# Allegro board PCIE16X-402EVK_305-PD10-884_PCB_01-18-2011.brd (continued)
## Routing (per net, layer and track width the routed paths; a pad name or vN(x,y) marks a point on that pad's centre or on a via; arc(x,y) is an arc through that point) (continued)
VIN1_2: length 48.1
  TOP w0.229: 80.58,35.2 79.84,35.2 79.83,35.19 v1(79.26,35.19) U2.24 ; U1.24 v1(63.26,35.19)
  TOP w0.635: 80.58,35.2 81.98,35.2
  TOP w0.762: v1(92.19,27.96) 89.83,27.96 87.49,30.3 87.49,32.51 84.8,35.2 81.98,35.2
  POWER1 w0.229: 64.58,35.2 64.58,35.19 v1(63.26,35.19) ; 78.4,35.19 v1(79.26,35.19)
  POWER1 w0.292: 64.58,35.2 65.13,35.2 65.43,35.49 ; 78.04,35.19 78.4,35.19
  POWER1 w0.508: 77.33,36.83 77.62,36.53 77.62,35.47 77.9,35.19 78.04,35.19
  POWER1 w0.635: 65.43,35.49 66.03,36.09 66.03,36.73
  POWER1 w0.762: 66.03,36.73 66.03,37.44 66.89,38.3 68.54,38.3 69.63,37.21 76.95,37.21 77.33,36.83
  BOTTOM w0.762: v1(92.19,27.96) 94.74,25.41 C160.2 95.86,25.41 96.25,25.8 97.47,25.8 97.51,25.84 C21.2
VIN3_4: length 46.4
  TOP w0.229: U3.24 v1(113.83,35.19) ; U4.24 v1(129.83,35.19)
  BOTTOM w0.229: 115.15,35.19 v1(113.83,35.19)
  BOTTOM w0.292: 115.15,35.19 115.63,35.19 116.4,35.96 116.4,37.59 117.08,38.27 ; v1(129.83,35.19) 129.8,35.23 129.02,35.23 128.38,35.86 128.38,36.47
  BOTTOM w0.635: 128.38,36.47 128.38,37.31 127.69,38.01
  BOTTOM w0.762: 127.69,38.01 126.02,39.67 118.48,39.67 117.08,38.27 ; C161.2 97.08,40.65 J5.2 97.69,41.08 C22.2 v1(101.08,41.08) 111.05,41.08 112.89,39.24 112.89,35.58 113.28,35.19 v1(113.83,35.19)
3_3V: length 25.6
  TOP w0.508: v1(52.51,57.48) 52.51,58.33 52.65,58.47 J2.B8 ; J1.B8 52.65,6.62 v1(52.34,6.93) ; U5.4 v1(86.8,18.69)
  BOTTOM w0.305: v1(54.06,7.52) 53.65,7.1 J1.A9
  BOTTOM w0.381: R6.1 v1(86.17,41.55)
  BOTTOM w0.508: v1(86.8,18.69) 86.69,18.8 C23.2 ; J2.A9 v1(53.65,57.73) ; J2.A10 v1(54.65,57.76) ; v1(54.12,6.8) 54.65,6.27 J1.A10
  BOTTOM w0.635: v1(52.51,57.48) 52.76,57.73 v1(53.65,57.73) 54.62,57.73 v1(54.65,57.76) ; R3.1 v1(88.53,22.88)
  vias: v1(82.11,36.73) v1(82.74,36.73) v1(83.5,36.73)
3_3VAUX: length 66.4
  TOP w0.292: J2.B10 54.65,58.59 55.18,58.06 55.18,57.3 54.14,56.26 50.61,56.26 46.01,51.66 46.01,16.99 54.65,8.35 J1.B10
A_D1: length 130.8
  TOP w0.229: 63.23,36.98 62.95,36.69 U1.27
  TOP w0.254: R7.2 v1(87.91,49.07)
  TOP w0.292: 63.23,36.98 63.31,37.06 v1(63.84,37.06) ; SW9.8 v1(140.66,20)
  POWER1 w0.292: v1(87.91,49.07) 82.49,49.07 74.59,41.17 65.82,41.17 63.84,39.19 v1(63.84,37.06) 63.23,37.06 62.67,36.5 62.67,30.07 68.49,24.25 124.27,24.25 127.65,27.63 139.31,27.63 140.65,26.29 140.65,20 v1(140.66,20)
A_D2: length 124.6
  TOP w0.229: U2.27 v1(79.99,36.69)
  TOP w0.254: R8.2 v1(87.01,47.62)
  TOP w0.292: SW9.7 143.67,22.54 v1(144.06,22.15)
  POWER1 w0.292: v1(150.81,41.86) 135.45,41.86 132.73,44.57 103.31,44.57 98.46,39.72 92.39,39.72 90.53,37.87 81.17,37.87 v1(79.99,36.69) 79.16,37.52 79.16,43.61 83.17,47.62 v1(87.01,47.62)
  BOTTOM w0.292: v1(144.06,22.15) 144.13,22.07 149.85,22.07 153.38,25.6 153.38,39.29 v1(150.81,41.86)
A_D3: length 51.2
  TOP w0.229: U3.27 v1(114.56,36.69)
  TOP w0.254: v1(135.27,40.43) 134.72,39.89 R9.2
  TOP w0.292: R9.2 134.05,26.03 135.51,24.57 140.16,24.57 140.66,25.08 SW9.6
  BOTTOM w0.292: v1(114.56,36.69) 114.56,40.01 116.18,41.63 116.2,41.63 116.22,41.64 133.82,41.64 133.84,41.63 134.07,41.63 v1(135.27,40.43)
A_D4: length 27.1
  TOP w0.229: U4.27 v1(130.56,36.69)
  TOP w0.254: R10.2 v1(137.88,40.01)
  TOP w0.292: SW9.5 142.28,27.63 140.14,27.63 138.01,29.77 138.01,37.89 136.97,38.93 R10.2
  BOTTOM w0.292: v1(130.56,36.69) 131.3,36.69 134,39.39 137.26,39.39 v1(137.88,40.01)
DEMA0_SDA: length 139
  TOP w0.229: U4.49 v1(118.2,35.19) ; U3.49 v1(102.2,35.19) ; U1.49 v1(51.62,35.19) ; U2.49 v1(67.63,35.19)
  TOP w0.292: SW3.12 SW3.10 22.67,37.61 23.41,36.88 33.41,36.88 42.23,45.69 SW4.1 v1(42.23,49.82)
  POWER1 w0.229: 116.88,35.19 v1(118.2,35.19)
  POWER1 w0.292: v1(102.2,35.19) 102.75,35.19 102.98,35.43 103,35.43 103.33,35.76 103.33,35.77 103.34,35.79 103.34,37.46 104.84,38.96 114.62,38.96 115.56,38.02 115.56,36.31 116.68,35.19 116.88,35.19 ; v1(42.23,49.82) 42.23,48.1 52.17,38.16 52.17,35.74 v1(51.62,35.19)
  BOTTOM w0.229: v1(102.2,35.19) 100.88,35.19 ; 66.31,35.19 v1(67.63,35.19)
  BOTTOM w0.292: v1(51.62,35.19) 52.46,35.19 52.87,35.61 52.87,37.79 54.64,39.56 62.81,39.56 65.03,37.34 65.03,35.89 65.73,35.2 66.15,35.2 66.16,35.19 66.31,35.19 ; 100.88,35.19 100.38,35.19 98.11,37.46 80.86,37.46 79.02,39.3 70.64,39.3 69.01,37.68 69.01,35.88 68.9,35.77 68.9,35.76 68.34,35.2 67.63,35.2 v1(67.63,35.19)
DEMA1_SCL: length 141
  TOP w0.229: U2.50 v1(66.9,34.69) ; U4.50 v1(117.47,34.69) ; U3.50 v1(101.47,34.69) ; U1.50 v1(50.9,34.69)
  TOP w0.292: 25.21,39.37 SW3.8 SW3.7 30.48,39.19 33.44,39.19 39.69,45.44 SW4.2 v1(39.69,49.89)
  POWER1 w0.229: 51.93,34.7 51.93,34.69 v1(50.9,34.69)
  POWER1 w0.292: 51.93,34.7 52.29,34.7 52.68,35.09 52.68,38.3 52.69,38.31 52.69,38.76 44.77,46.68 44.77,48.46 42.56,50.67 40.46,50.67 v1(39.69,49.89)
  BOTTOM w0.229: 102.48,34.7 101.47,34.7 v1(101.47,34.69) ; v1(50.9,34.69) 52.01,34.69 ; v1(66.9,34.69) 68.42,34.69
  BOTTOM w0.292: 52.01,34.69 52.72,34.69 53.38,35.35 53.38,37.46 54.97,39.05 62.6,39.05 64.52,37.13 64.52,35.68 65.52,34.69 66.89,34.69 v1(66.9,34.69) ; v1(117.47,34.69) 116.95,34.69 115.56,33.3 115.56,32.51 115,31.95 113.27,31.95 112.13,33.09 112.13,38.43 111.39,39.16 104.48,39.16 103.65,38.33 103.65,35.48 102.86,34.7 102.48,34.7 ; v1(101.47,34.69) 99.91,34.69 98.67,35.94 81.62,35.94 78.77,38.8 70.97,38.8 69.51,37.33 69.51,35.63 68.57,34.69 68.42,34.69
DEMB0_AD1: length 117.1
  TOP w0.229: U4.53 v1(118.2,33.19) ; U1.53 v1(51.62,33.19) ; U3.53 v1(102.2,33.19) ; U2.53 v1(67.63,33.19)
  TOP w0.292: 17.84,26.55 SW5.11 22.92,26.55 v1(22.92,28.34)
  POWER1 w0.229: 50.23,33.19 v1(51.62,33.19)
  POWER1 w0.292: v1(22.92,28.34) 28.36,33.78 49.64,33.78 50.23,33.19
  BOTTOM w0.229: v1(118.2,33.19) 118.2,33.19 117.21,33.19 116.88,32.86 ; v1(67.63,33.19) 66.41,33.19 66.31,33.09 ; 100.96,33.19 v1(102.2,33.19)
  BOTTOM w0.292: v1(102.2,33.19) 105.47,29.92 115.1,29.92 116.8,31.62 116.8,32.79 116.88,32.86 ; v1(67.63,33.19) 68.42,33.19 71.73,29.88 85.01,29.88 86.3,31.16 97.35,31.16 99.38,33.19 100.96,33.19 ; 66.31,33.09 63.3,30.08 54.71,30.08 51.62,33.17 v1(51.62,33.19)
DEMB1_AD0: length 110
  TOP w0.229: U1.54 v1(50.9,32.69) ; U2.54 v1(66.9,32.69) ; U4.54 v1(117.47,32.69) ; U3.54 v1(101.47,32.69)
  TOP w0.292: v1(31.72,26.55) SW5.7 SW5.9
  POWER1 w0.292: v1(31.72,26.55) 35.5,30.32 47.05,30.32 49.42,32.69 v1(50.9,32.69)
  BOTTOM w0.292: v1(117.47,32.69) 117.47,31.32 115.51,29.36 105.23,29.36 101.89,32.69 v1(101.47,32.69) 99.78,32.69 97.62,30.53 94.07,30.53 92.93,29.38 71.46,29.38 68.19,32.66 67.85,32.66 67.85,32.66 67.4,32.66 67.4,32.66 66.93,32.66 v1(66.9,32.69) 63.78,29.58 54.01,29.58 v1(50.9,32.69)
ENSMB: length 122.3
  TOP w0.229: U3.48 v1(101.47,35.69) ; U2.48 v1(66.9,35.69) ; U4.48 v1(117.47,35.69) ; U1.48 v1(50.9,35.69)
  TOP w0.292: v1(27.37,43.09) SW2.6 SW2.5 SW2.4
  POWER1 w0.229: v1(101.47,35.69) 102.56,35.69 102.79,35.92
  POWER1 w0.292: v1(27.37,43.09) 35.56,43.09 42.96,35.69 v1(50.9,35.69) ; v1(117.47,35.69) 117.44,35.72 116.89,35.72 116.17,36.45 116.17,38.3 115,39.47 104.46,39.47 102.83,37.84 102.83,35.96 102.79,35.92
  BOTTOM w0.229: v1(50.9,35.69) 51.88,35.69 ; 68.31,35.89 68.12,35.69 v1(66.9,35.69)
  BOTTOM w0.292: v1(66.9,35.69) 66.17,35.69 65.54,36.33 65.54,37.59 63.06,40.07 54.33,40.07 52.36,38.1 52.36,35.94 52.12,35.69 51.88,35.69 ; 68.31,35.89 68.52,36.09 68.52,38.07 70.27,39.82 79.22,39.82 81.07,37.97 98.62,37.97 100.88,35.71 101.45,35.71 v1(101.47,35.69)
EQA0: length 121.6
  TOP w0.229: U3.20 v1(113.83,33.19) ; U2.20 v1(79.26,33.19) ; U4.20 v1(129.83,33.19) ; U1.20 v1(63.26,33.19)
  TOP w0.292: SW11.12 SW11.11 SW11.10 v1(154.19,24.78)
  POWER1 w0.229: 131.15,33.4 130.95,33.19 v1(129.83,33.19) ; v1(113.83,33.19) 113.83,33.19 114.85,33.19 ; v1(63.26,33.19) 64.3,33.19 64.58,32.92 ; v1(79.26,33.19) 80.58,33.19
  POWER1 w0.292: v1(113.83,33.19) 113.83,32.15 111.65,29.97 84.87,29.97 81.65,33.19 80.58,33.19 ; v1(154.19,24.78) 154.19,30.61 151.83,32.97 143.57,32.97 140.93,35.61 133.36,35.61 131.15,33.4 ; 114.85,33.19 115.1,33.19 115.76,32.53 115.76,31.52 117.46,29.82 127.14,29.82 129.81,32.48 129.81,33.17 v1(129.83,33.19) ; 64.58,32.92 64.76,32.74 64.76,31.14 66.69,29.21 76.59,29.21 79.26,31.88 v1(79.26,33.19)
EQA1: length 114.8
  TOP w0.229: U4.19 v1(130.56,32.69) ; U3.19 v1(114.56,32.69) ; U2.19 v1(79.99,32.69) ; U1.19 v1(63.99,32.69)
  TOP w0.292: SW11.9 SW11.8 SW11.7 v1(152.17,31.43)
  POWER1 w0.292: v1(63.99,32.69) 63.99,30.99 66.28,28.7 76.85,28.7 79.77,31.62 79.77,32.47 v1(79.99,32.69) 80,32.69 81.42,32.69 84.57,29.54 84.61,29.54 84.67,29.47 111.85,29.47 111.92,29.54 111.98,29.54 114.36,31.92 114.36,32.5 v1(114.56,32.69) 114.81,32.69 115.25,32.25 115.25,31.16 117.11,29.31 127.88,29.31 130.56,31.99 v1(130.56,32.69) 130.59,32.72 132.31,32.72 134.46,30.58 151.31,30.58 v1(152.17,31.43)
EQB0_AD3: length 123.9
  TOP w0.229: U1.46 v1(50.9,36.69) ; U4.46 v1(117.47,36.69) ; U2.46 v1(66.9,36.69) ; U3.46 v1(101.47,36.69)
  TOP w0.292: v1(32.77,55.29) SW1.12 SW1.11 SW1.10
  POWER1 w0.292: v1(32.77,55.29) 32.77,51.41 47.47,36.71 50.88,36.71 v1(50.9,36.69) ; v1(117.47,36.69) 117.47,38.78 115.76,40.48 103.39,40.48 101.47,38.56 v1(101.47,36.69)
  BOTTOM w0.292: v1(101.47,36.69) 98.51,39.65 93.99,39.65 91.05,42.59 78.32,42.59 76.62,40.89 69.51,40.89 67.25,38.63 67.25,37 66.92,36.67 v1(66.9,36.69) 66.56,37.03 66.56,38 63.33,41.23 53.95,41.23 50.9,38.18 v1(50.9,36.69)
EQB1_AD2: length 126.2
  TOP w0.229: U4.47 v1(118.2,36.19) ; U1.47 v1(51.62,36.19) ; U3.47 v1(102.2,36.19) ; U2.47 v1(67.63,36.19)
  TOP w0.292: SW1.7 SW1.8 SW1.9 v1(25.08,55.29)
  POWER1 w0.229: 50.23,36.19 v1(51.62,36.19) ; v1(118.2,36.19) 117.21,36.19 116.88,36.52
  POWER1 w0.292: 50.23,36.19 44.21,36.19 25.12,55.29 v1(25.08,55.29) ; 116.88,36.52 116.68,36.73 116.68,38.71 115.41,39.98 104.15,39.98 102.2,38.02 v1(102.2,36.19)
  BOTTOM w0.229: v1(102.2,36.19) 101.1,36.19 100.88,36.41 ; 66.31,36.5 66.61,36.19 v1(67.63,36.19)
  BOTTOM w0.292: v1(51.62,36.19) 51.62,36.8 51.63,36.8 51.63,38.12 54.17,40.67 63.18,40.67 66.05,37.8 66.05,36.76 66.31,36.5 ; v1(67.63,36.19) 67.78,36.35 67.78,38.27 69.84,40.33 79.43,40.33 80.6,39.16 93.78,39.16 93.79,39.15 98.14,39.15 100.88,36.41
JTAG1: length 65
  TOP w0.292: J2.B9 53.65,58.61 53.12,58.08 53.12,57.22 52.68,56.79 50.18,56.79 45.38,51.99 45.38,16.43 53.26,8.55 53.26,6.44 53.65,6.05 J1.B9
JTAG2: length 66.7
  BOTTOM w0.292: J1.A5 49.65,13.38 37.61,25.42 37.61,43.58 49.65,55.63 J2.A5
JTAG3: length 67
  BOTTOM w0.292: J2.A6 50.65,58.46 50.15,57.95 50.15,55.01 38.27,43.13 38.27,25.98 50.2,14.04 50.2,6.36 50.65,5.91 J1.A6
JTAG4: length 67.2
  BOTTOM w0.292: J2.A7 51.65,58.67 50.64,57.66 50.64,54.56 38.95,42.87 38.95,26.31 51.02,14.25 51.02,6.5 51.65,5.86 J1.A7
JTAG5: length 67.6
  BOTTOM w0.292: J1.A8 52.65,5.79 52.87,6.01 52.87,13.38 39.69,26.57 39.69,42.72 51.72,54.75 51.72,57.78 52.65,58.7 J2.A8
LPBK: length 138.1
  TOP w0.229: U2.23 v1(79.99,34.69) ; U4.23 v1(130.56,34.69) ; U3.23 v1(114.56,34.69) ; U1.23 v1(63.99,34.69)
  TOP w0.292: v1(139.03,57.25) SW6.9 SW6.8 SW6.7
  POWER1 w0.229: 78.02,34.36 78.35,34.69 v1(79.99,34.69) ; 112.73,34.45 112.97,34.69 v1(114.56,34.69)
  POWER1 w0.292: 112.73,34.45 112.73,34.45 112.18,33.9 112.18,33.04 111.42,32.28 106.53,32.28 105.72,31.47 91.25,31.47 90.42,32.3 84.8,32.3 82.41,34.69 v1(79.99,34.69) ; 78.02,34.36 75.58,31.92 66.84,31.92 66.31,32.46 66.31,33.53 65.68,34.16 65.14,34.7 64,34.7 v1(63.99,34.69)
  BOTTOM w0.229: v1(130.56,34.69) 129.2,34.69
  BOTTOM w0.292: v1(114.56,34.69) 114.61,34.64 116.2,34.64 116.75,35.19 116.75,35.2 116.94,35.39 116.94,36.91 116.95,36.92 116.95,36.95 118.81,38.81 125.04,38.81 127.65,36.19 127.65,36.17 127.8,36.02 127.8,35.72 128.79,34.73 128.83,34.73 128.87,34.69 129.2,34.69 ; v1(139.03,57.25) 139.03,53.95 149.06,43.92 149.06,35.88 147.76,34.59 145.66,34.59 142.08,38.17 134.84,38.17 131.36,34.69 v1(130.56,34.69)
PERN0: length 4
  TOP w0.203: C64.1 52.31,28.9 52.31,29.91 53.67,31.27 53.67,32.02 U1.2
PERN0_C: length 3.9
  TOP w0.203: U1.44 53.67,37.36 53.67,38.3 52.34,39.63 52.34,40.51 C128.1
PERN1: length 3.8
  TOP w0.203: U1.4 54.67,32.02 54.67,30.87 53.84,30.03 53.84,28.9 C66.1
PERN1_C: length 3.8
  TOP w0.203: C130.1 53.84,40.49 53.84,39.53 54.67,38.7 54.67,37.36 U1.42
PERN2: length 3.5
  TOP w0.203: C68.1 55.39,28.87 55.39,30.16 55.67,30.45 55.67,32.02 U1.6
PERN2_C: length 3.7
  TOP w0.203: C132.1 55.36,40.49 55.36,39.63 56.17,38.82 56.17,37.36 U1.39
PERN3: length 3.5
  TOP w0.203: C70.1 56.93,28.85 56.93,30.1 56.67,30.36 56.67,32.02 U1.8
PERN3_C: length 3.5
  TOP w0.203: C134.1 56.88,40.49 56.88,39.45 57.17,39.17 57.17,37.36 U1.37
PERN4: length 4
  TOP w0.203: C72.1 68.31,28.9 68.31,29.86 69.67,31.21 69.67,32.02 U2.2
PERN4_C: length 3.9
  TOP w0.203: C136.1 68.34,40.51 68.34,39.63 69.67,38.3 69.67,37.36 U2.44
PERN5: length 3.8
  TOP w0.203: C74.1 69.84,28.9 69.84,29.98 70.67,30.82 70.67,32.02 U2.4
PERN5_C: length 3.8
  TOP w0.203: U2.42 70.67,37.36 70.67,38.7 69.84,39.53 69.84,40.49 C138.1
PERN6: length 3.5
  TOP w0.203: U2.6 71.67,32.02 71.67,30.45 71.39,30.16 71.39,28.87 C76.1
PERN6_C: length 3.7
  TOP w0.203: U2.39 72.17,37.36 72.17,38.82 71.36,39.63 71.36,40.49 C140.1
PERN7: length 3.5
  TOP w0.203: C78.1 72.94,28.85 72.94,30.1 72.67,30.36 72.67,32.02 U2.8
PERN7_C: length 3.5
  TOP w0.203: C142.1 72.89,40.49 72.89,39.45 73.17,39.17 73.17,37.36 U2.37
PERN8: length 4
  TOP w0.203: C80.1 102.88,28.9 102.88,29.86 104.24,31.21 104.24,32.02 U3.2
PERN8_C: length 3.9
  TOP w0.203: U3.44 104.24,37.36 104.24,38.3 102.91,39.63 102.91,40.51 C144.1
PERN9: length 3.8
  TOP w0.203: U3.4 105.24,32.02 105.24,30.82 104.41,29.98 104.41,28.9 C82.1
PERN9_C: length 3.8
  TOP w0.203: C146.1 104.41,40.49 104.41,39.53 105.24,38.7 105.24,37.36 U3.42
PERN10: length 3.5
  TOP w0.203: C84.1 105.96,28.87 105.96,30.16 106.24,30.45 106.24,32.02 U3.6
PERN10_C: length 3.7
  TOP w0.203: C148.1 105.93,40.49 105.93,39.63 106.74,38.82 106.74,37.36 U3.39
PERN11: length 3.5
  TOP w0.203: U3.8 107.24,32.02 107.24,30.36 107.51,30.1 107.51,28.85 C86.1
PERN11_C: length 3.5
  TOP w0.203: C150.1 107.46,40.49 107.46,39.45 107.74,39.17 107.74,37.36 U3.37
PERN12: length 4
  TOP w0.203: C88.1 118.89,28.9 118.89,29.86 120.24,31.21 120.24,32.02 U4.2
PERN12_C: length 3.9
  TOP w0.203: C152.1 118.91,40.51 118.91,39.63 120.24,38.3 120.24,37.36 U4.44
PERN13: length 3.8
  TOP w0.203: C90.1 120.41,28.9 120.41,29.98 121.24,30.82 121.24,32.02 U4.4
PERN13_C: length 3.8
  TOP w0.203: C154.1 120.41,40.49 120.41,39.53 121.24,38.7 121.24,37.36 U4.42
PERN14: length 3.5
  TOP w0.203: U4.6 122.24,32.02 122.24,30.45 121.96,30.16 121.96,28.87 C92.1
PERN14_C: length 3.7
  TOP w0.203: U4.39 122.74,37.36 122.74,38.82 121.93,39.63 121.93,40.49 C156.1
PERN15: length 3.5
  TOP w0.203: U4.8 123.24,32.02 123.24,30.36 123.51,30.1 123.51,28.85 C94.1
PERN15_C: length 3.5
  TOP w0.203: U4.37 123.74,37.36 123.74,39.17 123.46,39.45 123.46,40.49 C158.1
PERP0: length 3.9
  TOP w0.203: C63.1 51.85,28.85 51.85,30.1 53.21,31.46 53.21,32.02 U1.1
PERP0_C: length 3.9
  TOP w0.203: C127.1 51.88,40.51 51.88,39.44 53.21,38.11 53.21,37.36 U1.45
PERP1: length 3.7
  TOP w0.203: C65.1 53.38,28.85 53.38,30.22 54.21,31.06 54.21,32.02 U1.3
PERP1_C: length 3.7
  TOP w0.203: U1.43 54.21,37.36 54.21,38.51 53.38,39.34 53.38,40.54 C129.1
PERP2: length 3.5
  TOP w0.203: C67.1 54.93,28.87 54.93,30.35 55.21,30.64 55.21,32.02 U1.5
PERP2_C: length 3.7
  TOP w0.203: U1.40 55.71,37.36 55.71,38.63 54.9,39.44 54.9,40.54 C131.1
PERP3: length 3.5
  TOP w0.203: C69.1 56.48,28.9 56.48,29.91 56.21,30.17 56.21,32.02 U1.7
PERP3_C: length 3.5
  TOP w0.203: C133.1 56.43,40.54 56.43,39.27 56.71,38.98 56.71,37.36 U1.38
PERP4: length 3.9
  TOP w0.203: C71.1 67.86,28.85 67.86,30.04 69.22,31.4 69.22,32.02 U2.1
PERP4_C: length 3.9
  TOP w0.203: C135.1 67.88,40.51 67.88,39.44 69.22,38.11 69.22,37.36 U2.45
PERP5: length 3.7
  TOP w0.203: U2.3 70.22,32.02 70.22,31.01 69.38,30.17 69.38,28.85 C73.1
PERP5_C: length 3.7
  TOP w0.203: C137.1 69.38,40.54 69.38,39.34 70.22,38.51 70.22,37.36 U2.43
PERP6: length 3.5
  TOP w0.203: U2.5 71.22,32.02 71.22,30.64 70.93,30.35 70.93,28.87 C75.1
PERP6_C: length 3.7
  TOP w0.203: U2.40 71.72,37.36 71.72,38.63 70.9,39.44 70.9,40.54 C139.1
PERP7: length 3.5
  TOP w0.203: C77.1 72.48,28.9 72.48,29.91 72.22,30.17 72.22,32.02 U2.7
PERP7_C: length 3.5
  TOP w0.203: C141.1 72.43,40.54 72.43,39.27 72.72,38.98 72.72,37.36 U2.38
PERP8: length 3.9
  TOP w0.203: C79.1 102.43,28.85 102.43,30.04 103.79,31.4 103.79,32.02 U3.1
PERP8_C: length 3.9
  TOP w0.203: C143.1 102.45,40.51 102.45,39.44 103.79,38.11 103.79,37.36 U3.45
PERP9: length 3.7
  TOP w0.203: U3.3 104.79,32.02 104.79,31.01 103.95,30.17 103.95,28.85 C81.1
PERP9_C: length 3.7
  TOP w0.203: C145.1 103.95,40.54 103.95,39.34 104.79,38.51 104.79,37.36 U3.43
PERP10: length 3.5
  TOP w0.203: U3.5 105.79,32.02 105.79,30.64 105.5,30.35 105.5,28.87 C83.1
PERP10_C: length 3.7
  TOP w0.203: C147.1 105.47,40.54 105.47,39.44 106.29,38.63 106.29,37.36 U3.40
PERP11: length 3.5
  TOP w0.203: C85.1 107.05,28.9 107.05,29.91 106.79,30.17 106.79,32.02 U3.7
PERP11_C: length 3.5
  TOP w0.203: C149.1 107,40.54 107,39.27 107.29,38.98 107.29,37.36 U3.38
PERP12: length 3.9
  TOP w0.203: U4.1 119.79,32.02 119.79,31.4 118.43,30.04 118.43,28.85 C87.1
PERP12_C: length 3.9
  TOP w0.203: U4.45 119.79,37.36 119.79,38.11 118.45,39.44 118.45,40.51 C151.1
PERP13: length 3.7
  TOP w0.203: C89.1 119.95,28.85 119.95,30.17 120.79,31.01 120.79,32.02 U4.3
PERP13_C: length 3.7
  TOP w0.203: C153.1 119.95,40.54 119.95,39.34 120.79,38.51 120.79,37.36 U4.43
PERP14: length 3.5
  TOP w0.203: U4.5 121.79,32.02 121.79,30.64 121.5,30.35 121.5,28.87 C91.1
PERP14_C: length 3.7
  TOP w0.203: C155.1 121.48,40.54 121.48,39.44 122.29,38.63 122.29,37.36 U4.40
PERP15: length 3.5
  TOP w0.203: U4.7 122.79,32.02 122.79,30.17 123.05,29.91 123.05,28.9 C93.1
PERP15_C: length 3.5
  TOP w0.203: C157.1 123,40.54 123,39.27 123.29,38.98 123.29,37.36 U4.38
PERST: length 69.4
  BOTTOM w0.292: J1.A11 55.65,6.97 55.28,7.34 55.28,12.04 40.32,27 40.32,42.29 55.65,57.61 J2.A11
PETN0: length 3.5
  TOP w0.203: U1.11 58.17,32.02 58.17,30.41 58.46,30.12 58.46,28.85 C32.2
PETN0_C: length 3.5
  TOP w0.203: U1.34 58.67,37.36 58.67,39.22 58.41,39.48 58.41,40.49 C96.2
PETN1: length 3.7
  TOP w0.203: C34.2 59.98,28.85 59.98,29.94 59.17,30.75 59.17,32.02 U1.13
PETN1_C: length 3.5
  TOP w0.203: C98.2 59.96,40.51 59.96,39.04 59.67,38.75 59.67,37.36 U1.32
PETN2: length 3.7
  TOP w0.203: C36.2 61.51,28.85 61.51,30.04 60.67,30.88 60.67,32.02 U1.16
PETN2_C: length 3.7
  TOP w0.203: U1.30 60.67,37.36 60.67,38.38 61.51,39.21 61.51,40.54 C100.2
PETN3: length 3.9
  TOP w0.203: U1.18 61.67,32.02 61.67,31.28 63.01,29.94 63.01,28.87 C38.2
PETN3_C: length 3.9
  TOP w0.203: U1.28 61.67,37.36 61.67,37.98 63.03,39.34 63.03,40.54 C102.2
PETN4: length 3.5
  TOP w0.203: C40.2 74.46,28.85 74.46,30.12 74.17,30.41 74.17,32.02 U2.11
PETN4_C: length 3.5
  TOP w0.203: C104.2 74.41,40.49 74.41,39.48 74.67,39.22 74.67,37.36 U2.34
PETN5: length 3.7
  TOP w0.203: C42.2 75.98,28.85 75.98,29.94 75.17,30.75 75.17,32.02 U2.13
PETN5_C: length 3.5
  TOP w0.203: U2.32 75.67,37.36 75.67,38.75 75.96,39.04 75.96,40.51 C106.2
PETN6: length 3.7
  TOP w0.203: C44.2 77.51,28.85 77.51,30.04 76.67,30.88 76.67,32.02 U2.16
PETN6_C: length 3.7
  TOP w0.203: C108.2 77.51,40.54 77.51,39.21 76.67,38.38 76.67,37.36 U2.30
PETN7: length 3.9
  TOP w0.203: U2.18 77.67,32.02 77.67,31.28 79.01,29.94 79.01,28.87 C46.2
PETN7_C: length 3.9
  TOP w0.203: U2.28 77.67,37.36 77.67,37.98 79.03,39.34 79.03,40.54 C110.2
PETN8: length 3.5
  TOP w0.203: C48.2 109.03,28.85 109.03,30.12 108.74,30.41 108.74,32.02 U3.11
PETN8_C: length 3.5
  TOP w0.203: U3.34 109.24,37.36 109.24,39.22 108.98,39.48 108.98,40.49 C112.2
PETN9: length 3.7
  TOP w0.203: U3.13 109.74,32.02 109.74,30.75 110.55,29.94 110.55,28.85 C50.2
PETN9_C: length 3.5
  TOP w0.203: C114.2 110.53,40.51 110.53,39.04 110.24,38.75 110.24,37.36 U3.32
PETN10: length 3.7
  TOP w0.203: C52.2 112.08,28.85 112.08,30.04 111.24,30.88 111.24,32.02 U3.16
PETN10_C: length 3.7
  TOP w0.203: U3.30 111.24,37.36 111.24,38.38 112.08,39.21 112.08,40.54 C116.2
PETN11: length 3.9
  TOP w0.203: C54.2 113.58,28.87 113.58,29.94 112.24,31.28 112.24,32.02 U3.18
PETN11_C: length 3.9
  TOP w0.203: C118.2 113.6,40.54 113.6,39.34 112.24,37.98 112.24,37.36 U3.28
PETN12: length 3.5
  TOP w0.203: U4.11 124.74,32.02 124.74,30.41 125.03,30.12 125.03,28.85 C56.2
PETN12_C: length 3.5
  TOP w0.203: C120.2 124.98,40.49 124.98,39.48 125.24,39.22 125.24,37.36 U4.34
PETN13: length 3.7
  TOP w0.203: C58.2 126.56,28.85 126.56,29.94 125.74,30.75 125.74,32.02 U4.13
PETN13_C: length 3.5
  TOP w0.203: U4.32 126.24,37.36 126.24,38.75 126.53,39.04 126.53,40.51 C122.2
PETN14: length 3.7
  TOP w0.203: C60.2 128.08,28.85 128.08,30.04 127.24,30.88 127.24,32.02 U4.16
PETN14_C: length 3.7
  TOP w0.203: U4.30 127.24,37.36 127.24,38.38 128.08,39.21 128.08,40.54 C124.2
PETN15: length 3.9
  TOP w0.203: U4.18 128.24,32.02 128.24,31.28 129.58,29.94 129.58,28.87 C62.2
PETN15_C: length 3.9
  TOP w0.203: C126.2 129.6,40.54 129.6,39.34 128.24,37.98 128.24,37.36 U4.28
PETP0: length 3.5
  TOP w0.203: U1.10 57.71,32.02 57.71,30.22 58,29.93 58,28.9 C31.2
PETP0_C: length 3.5
  TOP w0.203: U1.35 58.21,37.36 58.21,39.03 57.95,39.29 57.95,40.54 C95.2
PETP1: length 3.7
  TOP w0.203: C33.2 59.53,28.9 59.53,29.75 58.71,30.57 58.71,32.02 U1.12
PETP1_C: length 3.5
  TOP w0.203: C97.2 59.5,40.51 59.5,39.23 59.21,38.94 59.21,37.36 U1.33
PETP2: length 3.8
  TOP w0.203: U1.15 60.21,32.02 60.21,30.69 61.05,29.86 61.05,28.9 C35.2
PETP2_C: length 3.8
  TOP w0.203: U1.31 60.21,37.36 60.21,38.57 61.05,39.4 61.05,40.49 C99.2
PETP3: length 3.9
  TOP w0.203: U1.17 61.21,32.02 61.21,31.09 62.55,29.75 62.55,28.87 C37.2
PETP3_C: length 4
  TOP w0.203: U1.29 61.21,37.36 61.21,38.17 62.57,39.53 62.57,40.49 C101.2
PETP4: length 3.5
  TOP w0.203: U2.10 73.72,32.02 73.72,30.22 74,29.93 74,28.9 C39.2
PETP4_C: length 3.5
  TOP w0.203: C103.2 73.95,40.54 73.95,39.29 74.22,39.03 74.22,37.36 U2.35
PETP5: length 3.7
  TOP w0.203: U2.12 74.72,32.02 74.72,30.57 75.53,29.75 75.53,28.9 C41.2
PETP5_C: length 3.5
  TOP w0.203: U2.33 75.22,37.36 75.22,38.94 75.5,39.23 75.5,40.51 C105.2
PETP6: length 3.8
  TOP w0.203: U2.15 76.22,32.02 76.22,30.69 77.05,29.86 77.05,28.9 C43.2
PETP6_C: length 3.8
  TOP w0.203: C107.2 77.05,40.49 77.05,39.4 76.22,38.57 76.22,37.36 U2.31
PETP7: length 3.9
  TOP w0.203: U2.17 77.22,32.02 77.22,31.09 78.55,29.75 78.55,28.87 C45.2
PETP7_C: length 4
  TOP w0.203: U2.29 77.22,37.36 77.22,38.17 78.58,39.53 78.58,40.49 C109.2
PETP8: length 3.5
  TOP w0.203: U3.10 108.29,32.02 108.29,30.22 108.57,29.93 108.57,28.9 C47.2
PETP8_C: length 3.5
  TOP w0.203: C111.2 108.52,40.54 108.52,39.29 108.79,39.03 108.79,37.36 U3.35
PETP9: length 3.7
  TOP w0.203: C49.2 110.1,28.9 110.1,29.75 109.29,30.57 109.29,32.02 U3.12
PETP9_C: length 3.5
  TOP w0.203: U3.33 109.79,37.36 109.79,38.94 110.07,39.23 110.07,40.51 C113.2
PETP10: length 3.8
  TOP w0.203: C51.2 111.62,28.9 111.62,29.86 110.79,30.69 110.79,32.02 U3.15
PETP10_C: length 3.8
  TOP w0.203: U3.31 110.79,37.36 110.79,38.57 111.62,39.4 111.62,40.49 C115.2
PETP11: length 3.9
  TOP w0.203: U3.17 111.79,32.02 111.79,31.09 113.12,29.75 113.12,28.87 C53.2
PETP11_C: length 4
  TOP w0.203: C117.2 113.14,40.49 113.14,39.53 111.79,38.17 111.79,37.36 U3.29
PETP12: length 3.5
  TOP w0.203: U4.10 124.29,32.02 124.29,30.22 124.57,29.93 124.57,28.9 C55.2
PETP12_C: length 3.5
  TOP w0.203: U4.35 124.79,37.36 124.79,39.03 124.52,39.29 124.52,40.54 C119.2
PETP13: length 3.7
  TOP w0.203: U4.12 125.29,32.02 125.29,30.57 126.1,29.75 126.1,28.9 C57.2
PETP13_C: length 3.5
  TOP w0.203: C121.2 126.07,40.51 126.07,39.23 125.79,38.94 125.79,37.36 U4.33
PETP14: length 3.8
  TOP w0.203: C59.2 127.62,28.9 127.62,29.86 126.79,30.69 126.79,32.02 U4.15
PETP14_C: length 3.8
  TOP w0.203: C123.2 127.62,40.49 127.62,39.4 126.79,38.57 126.79,37.36 U4.31
PETP15: length 3.9
  TOP w0.203: U4.17 127.79,32.02 127.79,31.09 129.12,29.75 129.12,28.87 C61.2
PETP15_C: length 4
  TOP w0.203: U4.29 127.79,37.36 127.79,38.17 129.15,39.53 129.15,40.49 C125.2
PRSNT: length 198.9
  TOP w0.229: U1.52 v1(50.9,33.69) ; U2.52 v1(66.9,33.69) ; U4.52 v1(117.47,33.69) ; U3.52 v1(101.47,33.69)
  TOP w0.292: SW9.4 v1(149.26,27.62) ; v1(161.46,54.65) SW14.5 SW14.6 SW14.7 SW14.8
  POWER1 w0.229: 118.81,33.93 118.57,33.69 v1(117.47,33.69)
  POWER1 w0.292: 118.81,33.93 119.65,34.77 119.65,37.56 121.29,39.2 150.75,39.2 153.78,42.24 153.78,52.47 155.97,54.65 v1(161.46,54.65) 162.24,53.87 162.24,26.13 159.35,23.24 151.83,23.24 149.19,25.88 149.19,27.54 v1(149.26,27.62)
  BOTTOM w0.229: 103.07,33.69 103.08,33.69 ; 103.07,33.69 103.26,33.69 103.27,33.69 ; 103.07,33.69 102.79,33.69 ; 68.97,33.4 68.68,33.69 v1(66.9,33.69) ; v1(50.9,33.69) 51.99,33.69 52.41,33.27 ; 102.79,33.69 v1(101.47,33.69) ; 102.79,33.69 102.79,33.69
  BOTTOM w0.292: 68.97,33.4 71.99,30.38 81.08,30.38 81.09,30.38 84.39,30.38 85.81,31.8 97.12,31.8 99.01,33.69 v1(101.47,33.69) ; 52.41,33.27 55.09,30.59 62.89,30.59 66,33.7 66.89,33.7 v1(66.9,33.69) ; v1(117.47,33.69) 116.9,33.69 116.14,32.94 116.14,31.87 114.74,30.48 106.48,30.48 103.27,33.69 102.8,33.69 102.79,33.69
PRSNT1: length 64.8
  BOTTOM w0.292: J2.A1 45.65,58.64 45.35,58.34 44.84,58.34 44.16,57.65 44.16,52.98 36.92,45.74 36.92,24.79 46.93,14.78 46.93,10.33 45.65,9.06 J1.A1
PRSNT2_1: length 159.6
  TOP w0.292: SW14.1 v1(151.33,63.34) ; v1(63.97,57.78) 63.65,58.1 J2.B17 ; v1(64.03,7.39) 63.65,7.01 J1.B17
  POWER1 w0.292: v1(151.33,63.34) 149.92,63.34 144.87,58.29 133.08,58.29 131.78,56.99 97.71,56.99 96.18,58.52 76.49,58.52 74.77,56.79 67.37,56.79 65.98,58.19 64.38,58.19 v1(63.97,57.78) 63.97,48.82 53.2,38.05 53.2,31.85 64.03,21.02 v1(64.03,7.39)
PRSNT2_2: length 153.6
  TOP w0.292: SW14.2 v1(154.47,60.8) ; J1.B31 77.51,3.68 77.51,7.29 v1(77.23,7.57) ; v1(77.69,56.87) 77.74,56.92 77.74,60.16 J2.B31
  POWER1 w0.292: v1(77.23,7.57) 77.23,11.63 60.34,28.51 60.34,40.67 75.18,55.51 76.35,55.51 77.69,56.84 v1(77.69,56.87) 77.69,57.68 78.02,58.01 80.35,58.01 80.59,57.77 80.59,57.77 80.9,57.46 81.21,57.15 96.69,57.15 97.35,56.5 145.69,56.5 150,60.8 v1(154.47,60.8)
PRSNT2_3: length 126.1
  TOP w0.292: SW14.3 v1(154.28,58.26) ; 94.42,56.45 v1(94.4,56.45) ; 94.42,56.45 94.42,56.43 94.65,56.66 J2.B48 ; 94.42,56.45 94.42,56.51 94.35,56.43 94.35,48.13 95.64,46.83 97.78,46.83 99.15,45.46 99.15,32.45 100.7,30.9 100.7,13.89 94.65,7.84 J1.B48
  POWER1 w0.292: v1(94.4,56.45) 94.42,56.45 94.42,56.45 95.26,55.62 147.49,55.62 150.13,58.26 v1(154.28,58.26)
PRSNT2_4: length 105.8
  TOP w0.292: J1.B81 127.65,5.89 126.2,7.34 126.2,13.87 126.38,14.04 126.38,14.05 128.96,16.63 133.46,16.63 134.76,17.93 134.76,22.04 133.08,23.72 133.08,23.74 133.06,23.76 133.06,37.06 131.72,38.39 131.72,46.87 127.97,50.63 v1(127.97,57.92) 127.65,58.23 J2.B81 ; SW14.4 v1(154.62,55.72)
  POWER1 w0.292: v1(127.97,57.92) 128.27,58.23 132.06,58.23 132.97,59.14 139.78,59.14 144.74,64.11 153.84,64.11 155.77,62.18 155.77,56.87 v1(154.62,55.72)
RATE: length 127.2
  TOP w0.229: U2.21 v1(79.99,33.69) ; U3.21 v1(114.56,33.69) ; U4.21 v1(130.56,33.69) ; U1.21 v1(63.99,33.69)
  TOP w0.292: SW10.7 SW10.8 SW10.9 v1(154.67,45.18)
  POWER1 w0.229: 78.78,33.55 78.92,33.69 v1(79.99,33.69) ; v1(114.56,33.69) 114.56,33.69 113.54,33.69 113.4,33.55 ; v1(130.56,33.69) 129.63,33.69 129.3,33.36
  POWER1 w0.292: 129.3,33.36 126.28,30.34 126.28,30.32 117.79,30.32 116.27,31.85 116.27,32.72 115.3,33.69 v1(114.56,33.69) ; 78.78,33.55 78.59,33.36 78.59,31.99 76.37,29.77 67.02,29.77 65.29,31.49 65.29,33.14 64.75,33.69 64,33.69 v1(63.99,33.69) ; 113.4,33.55 113.22,33.37 113.22,32.3 111.39,30.48 90.84,30.48 90.02,31.3 84.4,31.3 84.3,31.39 84.26,31.39 81.95,33.7 80,33.7 v1(79.99,33.69)
  BOTTOM w0.292: v1(130.56,33.69) 131.21,33.04 148.04,33.04 151.98,36.98 151.98,39.27 150.08,41.17 150.08,43.08 152.18,45.18 v1(154.67,45.18)
RD_EN2: length 97.6
  TOP w0.229: U2.26 v1(79.26,36.19)
  TOP w0.292: SW8.7 v1(147.12,40.48) 145.45,38.82 145.45,23.06 148.52,20 SW9.1
  POWER1 w0.229: v1(79.26,36.19) 80.58,36.19
  POWER1 w0.292: 80.58,36.19 80.66,36.19 81.83,37.36 90.74,37.36 92.6,39.21 101.16,39.21 103.14,41.2 146.41,41.2 v1(147.12,40.48)
RD_EN3: length 61.6
  TOP w0.229: U3.26 v1(113.83,36.19)
  TOP w0.292: SW8.6 v1(147.12,37.94) 146.01,36.83 146.01,23.85 147.32,22.54 SW9.2
  BOTTOM w0.229: v1(113.83,36.19) 114.8,36.19 115.15,36.55 115.15,36.98
  BOTTOM w0.292: 115.15,36.98 115.15,39.7 116.6,41.14 133.62,41.14 134.86,39.9 136.54,39.9 137.18,40.55 144.52,40.55 v1(147.12,37.94)
RD_EN4: length 36.3
  TOP w0.229: U4.26 v1(129.83,36.19)
  TOP w0.292: SW8.5 147.18,35.4 v1(147.03,35.56) 146.55,35.07 146.55,26.95 148.42,25.08 SW9.3
  BOTTOM w0.229: v1(129.83,36.19) 131.15,36.19 131.15,36.2
  BOTTOM w0.292: v1(147.03,35.56) 143.7,38.88 134.4,38.88 131.72,36.2 131.15,36.2
REFCLKN: length 74.9
  BOTTOM w0.292: J1.A14 60.65,5.97 61.28,6.6 61.28,8.07 41.62,27.73 41.62,42 55.77,56.16 58.98,56.16 60.65,57.83 J2.A14
REFCLKP: length 74.9
  BOTTOM w0.292: J2.A13 59.65,57.54 58.77,56.66 55.56,56.66 40.91,42.01 40.91,27.53 60.62,7.82 60.62,6.85 59.65,5.89 J1.A13
RSV2: length 75.9
  TOP w0.292: v1(76.85,56.92) 76.82,56.94 76.82,57.1 76.57,57.35 76.57,60.17 J2.B30 ; v1(76.54,7.57) 76.65,7.46 76.65,6.14 76.65,6.13 J1.B30
  POWER1 w0.292: v1(76.54,7.57) 76.54,10.92 56.07,31.39 56.07,39.37 72.71,56 75.93,56 v1(76.85,56.92)
RSVD: length 65.9
  POWER1 w0.292: v1(65.4,7.52) 65.4,7.54 65.22,7.71 65.22,21.07 54.6,31.7 54.6,38.74 65.19,49.33 v1(65.19,57.65)
  BOTTOM w0.292: J1.A19 65.65,7.26 v1(65.4,7.52) ; v1(65.19,57.65) 65.19,57.68 65.65,58.15 J2.A19
RSVD1: length 69.7
  TOP w0.292: J2.B12 58.65,58.51 55.26,55.11 51.27,55.11 47.36,51.2 47.36,17.9 55.11,10.16 57.37,10.16 58.65,8.87 J1.B12
RSVD2: length 66.3
  TOP w0.292: J1.B82 128.65,5.79 126.89,7.55 126.89,13.84 129.15,16.1 133.67,16.1 135.27,17.7 135.27,22.25 133.55,23.96 133.55,37.52 132.36,38.71 132.36,47.1 128.65,50.81 J2.B82
RSVD3: length 71.7
  POWER1 w0.292: v1(78.12,7.72) 78.12,12.19 61.67,28.64 61.67,41.3 75.39,55.01 76.59,55.01 78.21,56.63 78.21,57.37 v1(78.27,57.43)
  BOTTOM w0.254: v1(78.27,57.43) 78.27,58.09 78.65,58.47 J2.A32
  BOTTOM w0.292: J1.A32 78.85,3.74 78.85,6.98 v1(78.12,7.72)
RSVD4: length 72.3
  POWER1 w0.292: v1(79.34,57.43) 79.34,56.36 77.48,54.51 75.58,54.51 62.17,41.09 62.17,29.49 79.08,12.57 v1(79.08,7.79)
  BOTTOM w0.254: J2.A33 79.65,58.49 79.31,58.15 79.31,57.43 v1(79.34,57.43)
  BOTTOM w0.292: J1.A33 79.65,7.23 v1(79.08,7.79)
RSVD5: length 63.4
  TOP w0.292: v1(96,56.51) 94.91,55.42 94.91,48.41 95.97,47.34 98.08,47.34 99.7,45.72 99.7,32.62 101.21,31.11 101.21,13.31 96.33,8.42 v1(96.33,6.53)
  BOTTOM w0.292: v1(96.33,6.53) 96.65,6.21 J1.A50 ; v1(96,56.51) 96,56.99 96.65,57.64 J2.A50
RXDET: length 111.9
  TOP w0.229: U3.22 v1(113.83,34.19) ; U2.22 v1(79.26,34.19) ; U1.22 v1(63.26,34.19) ; U4.22 v1(129.83,34.19)
  TOP w0.292: SW10.10 SW10.11 SW10.12 v1(151.16,37.56)
  POWER1 w0.229: v1(113.83,34.19) 115.15,34.19 ; 80.58,34.2 80.38,34.2 80.37,34.19 v1(79.26,34.19) ; v1(63.26,34.19) 64.58,34.19
  POWER1 w0.292: 115.15,34.19 115.5,34.19 116.83,32.86 116.83,32.23 117.28,31.77 126.96,31.77 129.45,34.26 129.77,34.26 v1(129.83,34.19) ; 80.58,34.2 82.2,34.2 84.6,31.79 90.23,31.79 91.05,30.97 105.94,30.97 106.74,31.77 111.63,31.77 112.69,32.83 112.69,33.71 113.17,34.19 v1(113.83,34.19) ; 64.58,34.19 64.94,34.19 65.8,33.34 65.8,31.85 67.32,30.32 76.09,30.32 78.08,32.32 78.08,33.64 78.63,34.19 79.26,34.19 v1(79.26,34.19)
  BOTTOM w0.229: 131.15,34.19 v1(129.83,34.19)
  BOTTOM w0.292: 131.15,34.19 131.9,34.19 133.31,35.61 143.42,35.61 145,34.03 148.04,34.03 151.16,37.15 v1(151.16,37.56)
SCL: length 122.8
  TOP w0.292: SW4.3 39.56,39.39 SW12.4 39.56,32.76 40.46,31.87 v1(42.67,31.87)
  BOTTOM w0.292: v1(42.67,31.87) 46.37,28.16 72.79,28.16 77.15,23.8 100.11,23.8 100.53,23.8 101.54,24.81 101.54,27.3 102.48,28.24 124.98,28.24 130.05,23.17 J9.6 131.58,22.94 R55.1 134.54,23.64 135.07,24.18 136.94,24.18 137.63,24.86 137.63,30.22 J8.3
SD_TH: length 105.7
  TOP w0.229: v1(63.64,36.29) 63.54,36.19 U1.26
  TOP w0.292: SW8.1 v1(138.26,43.02) ; SW8.1 SW8.2 SW8.3 SW8.4 ; SW8.1 140.16,48.1 140.8,48.73 SW6.12 SW6.11 SW6.10
  POWER1 w0.292: v1(138.26,43.02) 137.65,43.02 132.34,48.33 82.69,48.33 74.64,40.28 66.73,40.28 66,40.28 64.43,38.71 64.43,36.85 63.87,36.29 v1(63.64,36.29)
SDA: length 111.3
  TOP w0.292: SW4.4 42.1,39.39 SW12.3 42.1,33.58 v1(42.72,32.96)
  BOTTOM w0.292: J8.4 136.06,29.23 134.51,27.68 R56.1 131.59,25.47 J9.5 128.56,25.71 125.52,28.75 102.27,28.75 101.03,27.51 101.03,25.02 100.32,24.3 77.81,24.3 73.28,28.84 46.84,28.84 v1(42.72,32.96)
SMCLK: length 65.1
  TOP w0.292: J2.B5 49.65,57.88 44.06,52.29 44.06,32.46 39.56,27.96 SW12.1 39.56,23.85 43.85,19.55 43.85,15.74 49.65,9.95 J1.B5
SMDAT: length 63.8
  TOP w0.292: J1.B6 50.65,9.91 44.51,16.05 44.51,20.24 42.1,22.65 SW12.2 42.1,27.94 44.72,30.55 44.72,52.17 50.65,58.1 J2.B6
VIH: length 14.6
  BOTTOM w0.508: R54.2 v1(136.64,20.51) ; R56.2 v1(136.58,25.47) ; R44.1 v1(157.85,18.73) ; R55.2 v1(136.58,22.94) ; R47.1 v1(157.73,26.35)
  BOTTOM w0.635: R41.1 v1(156.99,45.18) ; R17.1 v1(25.46,48.79) ; R11.1 v1(31.69,58.82) ; R35.1 v1(144.67,57.25) ; R20.1 v1(17.59,35.71) ; R26.1 v1(17.84,23.26) ; R53.1 v1(143.7,42.95) ; R38.1 v1(157.09,37.56) ; R14.1 v1(24.07,58.82) ; R32.1 v1(144.54,49.63) ; R23.1 v1(25.21,35.71) ; R29.1 v1(25.46,23.26)
  vias: v1(49.85,22.4) v1(49.8,21.28) v1(49.92,25.42) v1(49.9,24.51) v1(49.87,23.49) v1(86.04,17.04) v1(86.75,17.45) v1(86.78,16.71) v1(87.64,17.45) v1(87.67,16.71)
WAKE: length 66.4
  TOP w0.292: J1.B11 55.65,8.34 46.67,17.32 46.67,51.38 51.02,55.72 54.55,55.72 55.87,57.05 55.87,58.33 55.65,58.54 J2.B11
N14347575: length 5.6
  TOP w0.292: U5.6 92.22,19.96 92.52,20.27 92.97,20.27 R2.2 93.03,19.35 93.26,19.12 93.26,18.48 R1.1 93.67,18.45 94.15,17.98 94.55,17.98 C29.2
N14347651: length 2.6
  TOP w0.292: U5.1 v1(84.09,22.5)
  BOTTOM w0.254: C25.1 v1(84.09,22.5)
N14347847: length 2.9
  TOP w0.292: U5.8 v1(92.16,22.5)
  BOTTOM w0.254: v1(92.16,22.5) 91.75,22.91 90.66,22.91 R3.2
N14379250: length 2.9
  TOP w0.254: U6.1 v1(81.38,41.17)
  BOTTOM w0.254: v1(81.38,41.17) 81.51,41.3 C26.1
N14379574: length 6.1
  TOP w0.292: C30.2 91.48,37.41 91.17,37.72 90.66,37.72 R4.1 ; R4.1 89.74,38.63 U6.6 ; R4.1 R5.2
N14379914: length 3.2
  TOP w0.292: U6.8 89.5,41.17 89.65,41.32 89.65,41.7 v1(89.66,41.71)
  BOTTOM w0.254: R6.2 88.43,41.64 89.59,41.64 v1(89.66,41.71)
N14519010: length 20.7
  TOP w0.292: SW8.8 v1(147.13,43.02)
  BOTTOM w0.292: SW13.1 138.86,52.94 147.13,44.67 v1(147.13,43.02) 147.06,42.95 R53.2
N14524358: length 2.7
  BOTTOM w0.292: R52.2 140.89,23.15 140.87,23.17 J9.3
N14524360: length 2.9
  BOTTOM w0.292: J9.2 140.99,20.63 141.02,20.61 R51.2
N14524362: length 3.1
  BOTTOM w0.292: J9.1 137.86,18.09 137.83,18.06 R50.2
N14693554: length 3.2
  BOTTOM w0.292: J9.7 131.47,20.51 R54.1
N143603151: length 2.9
  TOP w0.292: SW1.4 v1(24.07,62.27)
  BOTTOM w0.292: R14.2 v1(24.07,62.27)
N143603431: length 2.9
  TOP w0.292: SW1.5 v1(21.53,62.16)
  BOTTOM w0.292: R15.2 v1(21.53,62.16)
N143603671: length 2.9
  TOP w0.292: SW1.3 v1(26.61,62.27)
  BOTTOM w0.292: R13.2 26.48,62.14 v1(26.61,62.27)
N143605131: length 2.9
  TOP w0.292: SW1.2 v1(29.15,62.27)
  BOTTOM w0.292: v1(29.15,62.27) 29.02,62.14 R12.2
N143605431: length 2.9
  TOP w0.292: SW1.6 v1(18.99,62.27)
  BOTTOM w0.292: R16.2 18.86,62.14 v1(18.99,62.27)
N143605671: length 2.9
  TOP w0.292: SW1.1 v1(31.69,62.27)
  BOTTOM w0.292: R11.2 v1(31.69,62.27)
N144765660: length 34.4
  TOP w0.203: C109.1 78.55,41.42 78.55,45.63 76.92,47.25 76.92,50.2 78.36,51.63 91.39,51.63 92.77,53.02 92.77,56.25 91.91,57.11 91.91,59.99 J2.B45
N144766261: length 32.6
  TOP w0.203: C142.2 72.91,41.42 72.91,42.6 v1(73.14,42.83)
  BOTTOM w0.203: v1(73.14,42.83) 72.91,43.06 72.91,43.51 74,44.6 81.52,44.6 94.37,57.45 94.37,59.97 J2.A48
N144766561: length 32.2
  TOP w0.203: v1(119.75,42.83) 119.98,42.6 119.98,41.42 C153.2
  BOTTOM w0.203: v1(119.75,42.83) 119.98,43.06 119.98,46.26 121.21,47.49 126.19,47.49 127.29,48.6 127.29,52.44 126.24,53.49 120.45,53.49 118.92,55.01 118.92,59.97 J2.A72
N144766980: length 34.9
  TOP w0.203: C99.1 61.02,41.42 61.02,44.03 59.29,45.77 56.16,45.77 54.85,47.08 54.85,50.58 56.36,52.09 65.13,52.09 69.91,56.88 69.91,59.98 J2.B23
N144767221: length 32.4
  TOP w0.203: C158.2 123.48,41.42 123.48,42.6 v1(123.71,42.83)
  BOTTOM w0.203: J2.A81 127.37,59.97 127.37,57.55 128.11,56.82 131.81,56.82 133.06,55.57 133.06,45.59 131.69,44.22 123.94,44.22 123.48,43.76 123.48,43.06 v1(123.71,42.83)
N144767760: length 34.7
  TOP w0.203: C123.1 127.6,41.42 127.6,44.46 125.66,46.4 118.39,46.4 116.98,47.81 116.98,51.01 118.37,52.4 122.81,52.4 123.41,52.99 123.41,56.04 122.84,56.61 121.77,56.61 120.92,57.47 120.92,59.98 J2.B74
N144768181: length 32.1
  TOP w0.203: C132.2 55.39,41.42 55.39,41.96 v1(55.61,42.19)
  BOTTOM w0.203: J2.A26 72.38,59.98 72.38,54.61 67.2,49.43 57.47,49.43 55.39,47.34 55.39,42.42 v1(55.61,42.19)
N144768421: length 32
  TOP w0.203: v1(54.09,42.83) 53.86,42.6 53.86,41.42 C130.2
  BOTTOM w0.203: v1(54.09,42.83) 53.86,43.06 53.86,44.17 52.74,45.28 52.74,48.71 55.13,51.1 64.91,51.1 68.36,54.56 68.36,59.96 J2.A22
N144768781: length 32.1
  TOP w0.203: C147.2 105.5,41.42 105.5,41.96 v1(105.27,42.19)
  BOTTOM w0.203: v1(105.27,42.19) 105.5,42.42 105.5,47.23 103.76,48.97 99.24,48.97 98.26,49.95 98.26,52.31 99.24,53.29 105.23,53.29 106.92,54.97 106.92,59.98 J2.A60
N144769021: length 32
  TOP w0.203: v1(102.22,42.19) 102.45,41.96 102.45,41.42 C143.2
  BOTTOM w0.203: v1(102.22,42.19) 102.45,42.42 102.45,43.29 99.65,46.1 93.3,46.1 91.99,47.41 91.99,53.37 94.64,56.03 97.6,56.03 98.92,57.35 98.92,59.98 J2.A52
N144769680: length 35
  TOP w0.203: C95.1 57.98,41.42 57.98,42.81 57.28,43.51 51.44,43.51 50.03,44.92 50.03,52.76 51.72,54.45 59.62,54.45 60.92,55.76 60.92,59.98 J2.B14
N144769921: length 32.2
  TOP w0.203: C154.2 120.43,41.42 120.43,42.6 v1(120.66,42.83)
  BOTTOM w0.203: J2.A73 119.38,59.98 119.38,55.2 120.64,53.95 126.43,53.95 127.75,52.63 127.75,48.41 126.38,47.04 121.4,47.04 120.43,46.07 120.43,43.06 v1(120.66,42.83)
N144770280: length 34.8
  TOP w0.203: J2.B38 84.37,59.96 84.37,55.5 83.07,54.2 75.35,54.2 69.56,48.41 69.56,46.66 70.5,45.72 74.51,45.72 75.96,44.27 75.96,41.42 C106.1
N144770640: length 34.8
  TOP w0.203: J2.B58 104.94,59.96 104.94,57.59 104.57,57.22 103.15,57.22 102.2,56.27 102.2,53.76 103.05,52.9 106.48,52.9 107.51,51.88 107.51,49.54 106.71,48.74 104.45,48.74 103.65,47.94 103.65,46.47 104.37,45.74 109.91,45.74 111.6,44.05 111.6,41.42 C115.1
N144770880: length 34.8
  TOP w0.203: C116.1 112.05,41.42 112.05,44.24 110.1,46.2 104.56,46.2 104.1,46.66 104.1,47.75 104.64,48.28 106.9,48.28 107.96,49.35 107.96,52.07 106.67,53.36 103.24,53.36 102.65,53.95 102.65,56.08 103.34,56.77 104.76,56.77 105.4,57.4 105.4,60 J2.B59
N144771181: length 32.4
  TOP w0.203: C137.2 69.41,41.42 69.41,42.6 v1(69.18,42.83)
  BOTTOM w0.203: v1(69.18,42.83) 69.41,43.06 69.41,46.01 71.99,48.59 81,48.59 87.01,54.59 87.01,56.47 85.94,57.54 85.94,59.96 J2.A39
N144771420: length 34.6
  TOP w0.203: C108.1 77.48,41.42 77.48,44.88 74.21,48.16 74.21,50.77 76.16,52.73 88.35,52.73 89.65,54.02 89.65,56.16 88.35,57.45 88.35,59.95 J2.B42
N144771900: length 34.4
  TOP w0.203: J2.B28 74.36,59.96 74.36,57.32 67.25,50.21 58.46,50.21 57.72,49.48 57.72,48.28 58.46,47.55 60.21,47.55 63.01,44.75 63.01,41.42 C102.1
N144772140: length 34.3
  TOP w0.203: J2.B78 124.9,59.99 124.9,52.03 124.06,51.18 119.05,51.18 118.25,50.38 118.25,48.5 119.05,47.7 127.46,47.7 129.12,46.04 129.12,41.42 128.97,41.27 C125.1
N144772500: length 34.8
  TOP w0.203: C120.1 125.01,41.42 125.01,43.3 124.04,44.27 117.11,44.27 113.04,48.33 110.86,48.33 110.38,48.82 110.38,50.24 110.86,50.72 113.96,50.72 114.77,51.53 114.77,54.81 113.37,56.21 113.37,59.97 J2.B67
N144772741: length 32.3
  TOP w0.203: v1(106.79,42.83) 107.02,42.6 107.02,41.42 C149.2
  BOTTOM w0.203: v1(106.79,42.83) 107.02,43.06 107.02,44.38 108.28,45.64 115.83,45.64 116.68,46.49 116.68,49.18 115.77,50.09 112.12,50.09 110.91,51.29 110.91,59.99 J2.A64
N144773341: length 32.6
  TOP w0.203: v1(72.22,42.83) 72.45,42.6 72.45,41.42 C141.2
  BOTTOM w0.203: v1(72.22,42.83) 72.45,43.06 72.45,43.7 73.81,45.06 81.33,45.06 93.92,57.64 93.92,59.98 J2.A47
N144773581: length 32.3
  TOP w0.203: C133.2 56.45,41.42 56.45,42.6 v1(56.22,42.83)
  BOTTOM w0.203: v1(56.22,42.83) 56.45,43.06 56.45,45.68 58.9,48.13 67.24,48.13 75.91,56.8 75.91,59.98 75.78,60.1 75.78,60.12 J2.A29
N144774000: length 34.7
  TOP w0.203: J2.B75 121.37,59.97 121.37,57.65 121.96,57.07 123.03,57.07 123.86,56.23 123.86,52.8 123,51.94 118.55,51.94 117.44,50.82 117.44,48 118.58,46.86 125.84,46.86 128.05,44.65 128.05,41.42 C124.1
N144774240: length 34.6
  TOP w0.203: C117.1 113.12,41.42 113.12,45.73 111.96,46.89 109.63,46.89 108.73,47.79 108.73,51.32 109.7,52.3 112.68,52.3 113.2,52.81 113.2,53.76 112.78,54.17 106.83,54.17 106.06,54.95 106.06,56.22 106.86,57.02 108.61,57.02 108.93,57.34 108.93,59.97 J2.B62
N144774480: length 35
  TOP w0.203: J2.B20 66.38,59.98 66.38,56.08 63.06,52.75 54.34,52.75 53.07,51.48 53.07,46.33 54.39,45.01 58.51,45.01 59.96,43.56 59.96,41.42 C98.1
N144775140: length 34.4
  TOP w0.203: J2.B46 92.37,59.96 92.37,57.3 93.23,56.44 93.23,52.83 91.58,51.18 78.55,51.18 77.38,50.01 77.38,47.44 79.01,45.82 79.01,41.42 79.16,41.27 C110.1
N144775501: length 32.1
  TOP w0.203: C156.2 121.96,41.42 121.96,41.96 v1(122.19,42.19)
  BOTTOM w0.203: J2.A77 123.38,59.98 123.38,56.61 124.55,55.44 129.05,55.44 130.57,53.92 130.57,47.04 129.12,45.59 123,45.59 121.96,44.55 121.96,42.42 v1(122.19,42.19)
N144776160: length 34.8
  TOP w0.203: J2.B55 101.38,59.98 101.38,52.9 102.07,52.22 106.01,52.22 106.69,51.53 106.69,49.98 106.11,49.4 102.81,49.4 102.15,48.74 102.15,45.77 102.86,45.06 109.39,45.06 110.53,43.91 110.53,41.42 C114.1
N144776640: length 34.9
  TOP w0.203: J2.B24 70.37,59.97 70.37,56.69 65.32,51.63 56.55,51.63 55.31,50.39 55.31,47.27 56.35,46.22 59.47,46.22 61.48,44.22 61.48,41.42 C100.1
N144776880: length 35
  TOP w0.203: C97.1 59.5,41.42 59.5,43.37 58.32,44.55 54.21,44.55 52.62,46.14 52.62,51.67 54.15,53.21 62.87,53.21 65.93,56.27 65.93,59.97 J2.B19
N144777181: length 31.9
  TOP w0.203: C151.2 118.45,41.42 118.45,41.96 v1(118.22,42.19)
  BOTTOM w0.203: v1(118.22,42.19) 118.45,42.42 118.45,47.48 120.02,49.04 123.62,49.04 124.35,49.77 124.35,51.27 123.6,52.02 116.56,52.02 114.92,53.66 114.92,59.97 J2.A68
N144777421: length 32.3
  TOP w0.203: v1(107.71,42.83) 107.48,42.6 107.48,41.42 C150.2
  BOTTOM w0.203: J2.A65 111.37,59.96 111.37,51.48 112.31,50.54 115.96,50.54 117.13,49.37 117.13,46.3 116.01,45.18 108.47,45.18 107.48,44.19 107.48,43.06 v1(107.71,42.83)
N144777781: length 32
  TOP w0.203: C144.2 102.91,41.42 102.91,41.96 v1(103.14,42.19)
  BOTTOM w0.203: v1(103.14,42.19) 102.91,42.42 102.91,43.48 99.84,46.55 93.49,46.55 92.44,47.6 92.44,53.18 94.83,55.57 97.79,55.57 99.38,57.16 99.38,59.98 J2.A53
N144778201: length 32
  TOP w0.203: C146.2 104.43,41.42 104.43,42.6 v1(104.66,42.83)
  BOTTOM w0.203: v1(104.66,42.83) 104.43,43.06 104.43,44.95 101.45,47.94 96.42,47.94 95.44,48.92 95.44,53.06 96.66,54.28 101.33,54.28 103.37,56.31 103.37,59.96 J2.A57
N144778500: length 35
  TOP w0.203: C122.1 126.53,41.42 126.53,43.99 124.83,45.69 117.62,45.69 116.12,47.19 116.12,52.23 116.97,53.08 120.52,53.08 121.22,53.78 121.22,55.56 120.47,56.31 117.95,56.31 117.39,56.87 117.39,59.98 J2.B71
N144778741: length 32.1
  TOP w0.203: C148.2 105.96,41.42 105.96,41.96 v1(106.19,42.19)
  BOTTOM w0.203: v1(106.19,42.19) 105.96,42.42 105.96,47.42 103.95,49.43 99.43,49.43 98.72,50.14 98.72,52.12 99.43,52.83 105.42,52.83 107.38,54.78 107.38,59.98 J2.A61
N144778981: length 32.1
  TOP w0.203: C140.2 71.39,41.42 71.39,41.96 v1(71.62,42.19)
  BOTTOM w0.203: J2.A44 90.36,59.96 90.36,55.39 81.47,46.5 73.14,46.5 71.39,44.75 71.39,42.42 v1(71.62,42.19)
N144779220: length 34.8
  TOP w0.203: C103.1 73.98,41.42 73.98,43.14 73.33,43.79 67.11,43.79 65.95,44.94 65.95,47.63 74.32,56 79.2,56 79.92,56.73 79.92,59.98 J2.B33
N144779460: length 34.4
  TOP w0.203: J2.B27 73.9,60 73.9,57.51 67.06,50.67 58.27,50.67 57.26,49.67 57.26,48.09 58.27,47.09 60.02,47.09 62.55,44.56 62.55,41.42 C101.1
N144780060: length 35
  TOP w0.203: J2.B70 116.93,59.97 116.93,56.68 117.76,55.85 120.28,55.85 120.76,55.37 120.76,53.97 120.33,53.54 116.78,53.54 115.66,52.42 115.66,47 117.43,45.23 124.64,45.23 126.07,43.8 126.07,41.42 C121.1
N144780361: length 32.1
  TOP w0.203: v1(70.7,42.19) 70.93,41.96 70.93,41.42 C139.2
  BOTTOM w0.203: J2.A43 89.9,59.99 89.9,55.58 81.28,46.96 72.95,46.96 70.93,44.94 70.93,42.42 v1(70.7,42.19)
N144780601: length 32.4
  TOP w0.203: v1(70.09,42.83) 69.86,42.6 69.86,41.42 C138.2
  BOTTOM w0.203: v1(70.09,42.83) 69.86,43.06 69.86,45.82 72.17,48.13 81.19,48.13 87.47,54.4 87.47,56.66 86.4,57.73 86.4,60 J2.A40
N144788221: length 32.4
  TOP w0.203: v1(122.8,42.83) 123.03,42.6 123.03,41.42 C157.2
  BOTTOM w0.203: J2.A80 126.91,59.99 126.91,57.36 127.92,56.36 131.62,56.36 132.6,55.38 132.6,45.78 131.5,44.68 123.75,44.68 123.03,43.95 123.03,43.06 v1(122.8,42.83)
N144788821: length 32
  TOP w0.203: v1(103.75,42.83) 103.98,42.6 103.98,41.42 C145.2
  BOTTOM w0.203: J2.A56 102.91,59.99 102.91,56.5 101.14,54.73 96.47,54.73 94.98,53.25 94.98,48.73 96.23,47.48 101.26,47.48 103.98,44.77 103.98,43.06 v1(103.75,42.83)
N144789240: length 34.9
  TOP w0.203: C111.1 108.55,41.42 108.55,43.11 108.08,43.58 101.45,43.58 100.39,44.64 100.39,47.66 99.62,48.43 96.83,48.43 95.72,49.54 95.72,52.13 96.55,52.96 98.93,52.96 99.53,53.55 99.53,55.59 99.14,55.98 97.74,55.98 96.91,56.8 96.91,59.97 96.79,60.1 96.79,60.11 J2.B50
N144789780: length 34.6
  TOP w0.203: C107.1 77.03,41.42 77.03,44.69 73.75,47.97 73.75,50.96 75.97,53.18 88.16,53.18 89.19,54.21 89.19,55.97 87.9,57.26 87.9,60 J2.B41
N144790260: length 34.6
  TOP w0.203: C118.1 113.58,41.42 113.58,45.92 112.15,47.34 109.82,47.34 109.18,47.98 109.18,51.13 109.89,51.84 112.87,51.84 113.65,52.63 113.65,53.95 112.97,54.63 107.02,54.63 106.52,55.14 106.52,56.03 107.05,56.56 108.8,56.56 109.39,57.15 109.39,59.98 J2.B63
N144790620: length 34.8
  TOP w0.203: J2.B34 80.38,59.98 80.38,56.54 79.39,55.55 74.51,55.55 66.41,47.44 66.41,45.13 67.3,44.24 73.52,44.24 74.44,43.33 74.44,41.42 C104.1
N144791101: length 32
  TOP w0.203: C129.2 53.4,41.42 53.4,42.6 v1(53.17,42.83)
  BOTTOM w0.203: J2.A21 67.91,59.99 67.91,54.75 64.72,51.56 54.94,51.56 52.29,48.9 52.29,45.1 53.4,43.98 53.4,43.06 v1(53.17,42.83)
N144791880: length 34.3
  TOP w0.203: J2.B79 125.36,59.96 125.36,51.84 124.24,50.72 119.24,50.72 118.71,50.19 118.71,48.69 119.24,48.16 127.65,48.16 129.58,46.22 129.58,41.45 129.73,41.3 C126.1
N144792241: length 31.9
  TOP w0.203: v1(51.65,42.19) 51.88,41.96 51.88,41.42 C127.2
  BOTTOM w0.203: J2.A16 62.9,59.99 62.9,57.08 64.15,55.84 64.15,54.06 63.2,53.11 53.93,53.11 50.05,49.23 50.05,45.15 51.88,43.32 51.88,42.42 v1(51.65,42.19)
N144792841: length 31.8
  TOP w0.203: C135.2 67.88,41.42 67.88,41.96 v1(67.65,42.19)
  BOTTOM w0.203: v1(67.65,42.19) 67.88,42.42 67.88,46.74 71.27,50.14 80.39,50.14 83.5,53.25 83.5,55.84 81.93,57.41 81.93,59.97 J2.A35
N144793080: length 34.8
  TOP w0.203: C119.1 124.55,41.42 124.55,43.11 123.85,43.81 116.92,43.81 112.85,47.88 110.67,47.88 109.92,48.63 109.92,50.43 110.67,51.18 113.77,51.18 114.31,51.72 114.31,54.62 112.92,56.02 112.92,59.98 J2.B66
N144793501: length 31.9
  TOP w0.203: C128.2 52.34,41.42 52.34,41.96 v1(52.57,42.19)
  BOTTOM w0.203: J2.A17 63.36,59.96 63.36,57.27 64.61,56.03 64.61,53.87 63.39,52.65 54.12,52.65 50.51,49.04 50.51,45.34 52.34,43.51 52.34,42.42 v1(52.57,42.19)
N144794040: length 34.8
  TOP w0.203: J2.B54 100.93,59.97 100.93,52.72 101.88,51.76 105.82,51.76 106.24,51.34 106.24,50.17 105.92,49.86 102.62,49.86 101.69,48.93 101.69,45.58 102.67,44.6 109.2,44.6 110.07,43.72 110.07,41.42 C113.1
N144794401: length 32.1
  TOP w0.203: C131.2 54.93,41.42 54.93,41.96 v1(54.7,42.19)
  BOTTOM w0.203: J2.A25 71.92,59.98 71.92,54.8 67.01,49.88 57.28,49.88 54.93,47.53 54.93,42.42 v1(54.7,42.19)
N144794701: length 32.3
  TOP w0.203: C134.2 56.91,41.42 56.91,42.6 v1(57.14,42.83)
  BOTTOM w0.203: J2.A30 76.37,59.96 76.37,56.61 67.42,47.67 59.09,47.67 56.91,45.49 56.91,43.06 v1(57.14,42.83)
N144795060: length 35
  TOP w0.203: C96.1 58.43,41.42 58.43,43 57.47,43.96 51.63,43.96 50.48,45.11 50.48,52.57 51.91,54 59.8,54 61.38,55.57 61.38,59.98 J2.B15
N144795421: length 32.1
  TOP w0.203: v1(121.27,42.19) 121.5,41.96 121.5,41.42 C155.2
  BOTTOM w0.203: v1(121.27,42.19) 121.5,42.42 121.5,44.74 122.81,46.05 128.93,46.05 130.11,47.23 130.11,53.73 128.86,54.99 124.36,54.99 122.92,56.42 122.92,59.97 J2.A76
N144795720: length 34.9
  TOP w0.203: J2.B51 97.37,59.97 97.37,56.99 97.93,56.44 99.33,56.44 99.99,55.78 99.99,53.36 99.12,52.5 96.74,52.5 96.18,51.94 96.18,49.73 97.02,48.89 99.81,48.89 100.85,47.85 100.85,44.83 101.64,44.04 108.27,44.04 109,43.3 109,41.42 C112.1
N144796260: length 34.8
  TOP w0.203: J2.B37 83.78,60.12 83.78,60.1 83.91,59.98 83.91,55.69 82.88,54.66 75.16,54.66 69.1,48.6 69.1,46.47 70.31,45.26 74.32,45.26 75.5,44.08 75.5,41.42 C105.1
N144796741: length 31.9
  TOP w0.203: v1(119.14,42.19) 118.91,41.96 118.91,41.42 C152.2
  BOTTOM w0.203: J2.A69 115.38,59.98 115.38,53.84 116.75,52.47 123.79,52.47 124.8,51.46 124.8,49.58 123.81,48.59 120.21,48.59 118.91,47.29 118.91,42.42 v1(119.14,42.19)
N144796981: length 31.8
  TOP w0.203: C136.2 68.34,41.42 68.34,41.96 v1(68.57,42.19)
  BOTTOM w0.203: v1(68.57,42.19) 68.34,42.42 68.34,46.55 71.46,49.68 80.58,49.68 83.96,53.06 83.96,56.03 82.39,57.6 82.39,59.98 J2.A36
N144870501: length 3.9
  TOP w0.292: SW2.3 v1(20.38,53.24)
  BOTTOM w0.292: v1(20.38,53.24) 20.26,53.11 R19.2
N144870781: length 4
  TOP w0.292: SW2.1 v1(25.46,53.31)
  BOTTOM w0.292: R17.2 v1(25.46,53.31)
N144871281: length 3.7
  TOP w0.292: SW2.2 v1(22.92,53.18)
  BOTTOM w0.292: R18.2 v1(22.92,53.18)
